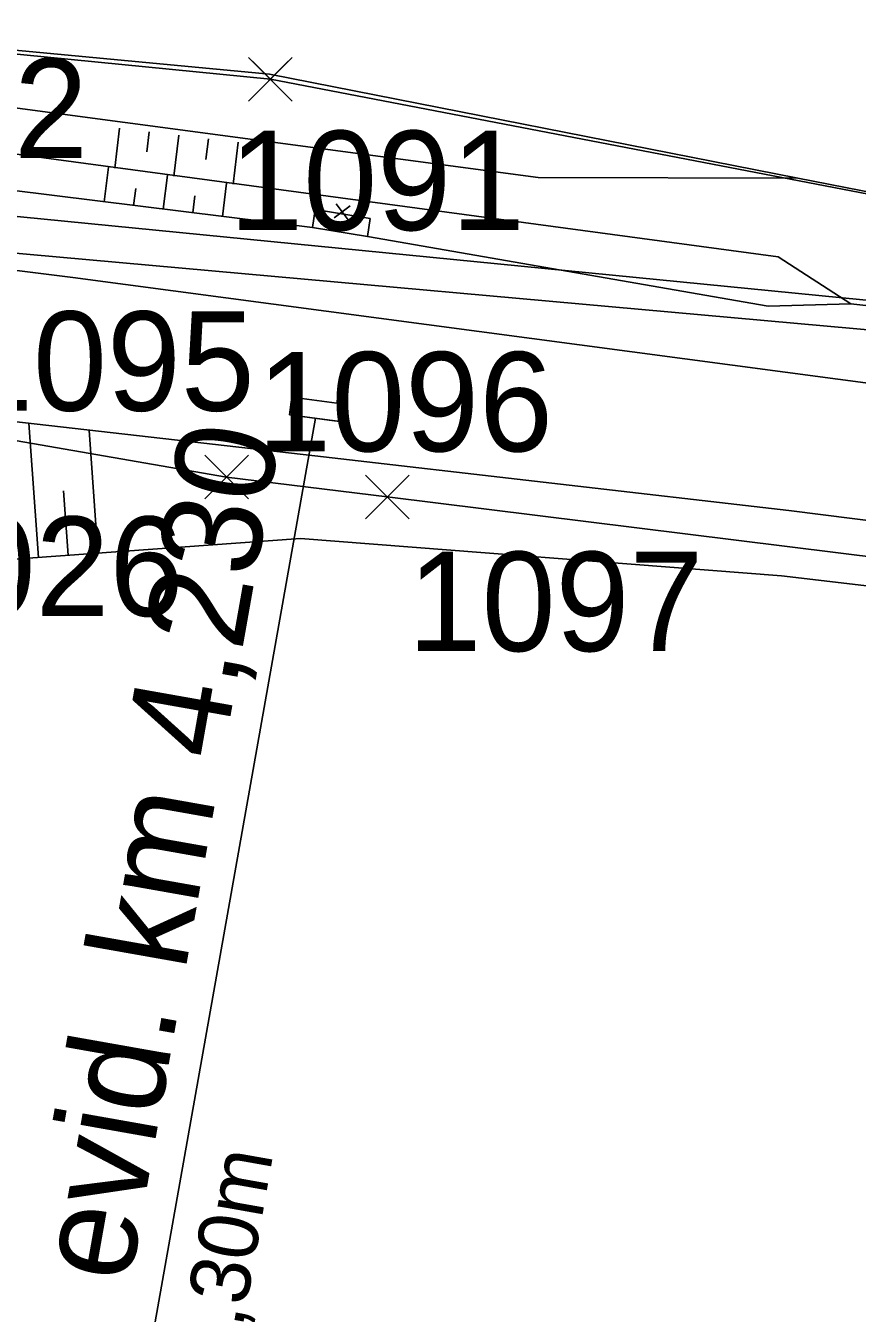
# Model space of a CAD drawing. Extents: x -738085 to -734426, y -1122197 to -1119748.
# Drawn here: x -737329.62 to -737308.71, y -1121446.65 to -1121414.26 of the extents above; entities that cross this region are included whole.
import ezdxf

# ---------------------------------------------------------------- set-up
doc = ezdxf.new("R2010")
doc.units = 0
for name, color, linetype in [('SŽDC', 7, 'Continuous'), ('Vrstva 1', 7, 'Continuous'), ('Vrstva 17', 7, 'Continuous'), ('Vrstva 19', 7, 'Continuous'), ('Vrstva 48', 7, 'Continuous'), ('Vrstva 49', 7, 'Continuous'), ('Vrstva 60', 7, 'Continuous'), ('Vrstva 63', 7, 'Continuous')]:
    doc.layers.add(name, color=color, linetype=linetype)

msp = doc.modelspace()

# ---------------------------------------------------------------- linework, layer by layer
at = {"layer": 'SŽDC'}
for p, q in [((-737336.44, -1121414.32), (-737323.47, -1121415.6)), ((-737323.47, -1121415.6), (-737307.99, -1121418.58)), ((-737296.15, -1121429.13), (-737320.53, -1121426.11))]:
    msp.add_line(p, q, dxfattribs=at)
msp.add_lwpolyline([(-737320.53, -1121426.11), (-737324.57, -1121425.61), (-737331.3, -1121424.45)], dxfattribs=at)
at = {"layer": 'Vrstva 1'}
msp.add_lwpolyline([(-737302.818, -1121423.992), (-737322.068, -1121421.435), (-737328.438, -1121420.593), (-737334.371, -1121419.848), (-737341.175, -1121419.077), (-737346.172, -1121418.626), (-737355.365, -1121418.093), (-737364.193, -1121418.049), (-737371.056, -1121418.37), (-737378.944, -1121419.134), (-737386.424, -1121420.242), (-737394.37, -1121421.821), (-737402.265, -1121423.869), (-737409.266, -1121426.074), (-737416.847, -1121428.911), (-737423.861, -1121431.965), (-737430.654, -1121435.335), (-737438.054, -1121439.528), (-737442.947, -1121442.622), (-737447.091, -1121445.439), (-737453.01, -1121449.85), (-737458.733, -1121454.549), (-737464.941, -1121460.218), (-737469.915, -1121465.238)], dxfattribs=at)
msp.add_lwpolyline([(-737302.818, -1121423.992), (-737322.068, -1121421.435), (-737328.438, -1121420.593), (-737334.371, -1121419.848), (-737341.175, -1121419.077), (-737346.172, -1121418.626), (-737355.365, -1121418.093), (-737364.193, -1121418.049), (-737371.056, -1121418.37), (-737378.944, -1121419.134), (-737386.424, -1121420.242), (-737394.37, -1121421.821), (-737402.265, -1121423.869), (-737409.266, -1121426.074), (-737416.847, -1121428.911), (-737423.861, -1121431.965), (-737430.654, -1121435.335), (-737438.054, -1121439.528), (-737442.947, -1121442.622), (-737447.091, -1121445.439), (-737453.01, -1121449.85), (-737458.733, -1121454.549), (-737464.941, -1121460.218), (-737469.915, -1121465.238)], dxfattribs=at)
at = {"layer": 'Vrstva 17'}
msp.add_lwpolyline([(-737220.546, -1121428.935), (-737265.552, -1121424.89), (-737285.353, -1121422.953), (-737310.199, -1121418.093), (-737323.493, -1121415.476), (-737336.393, -1121414.255)], dxfattribs=at)
at = {"layer": 'Vrstva 19'}
for p, q in [((-737322.341, -1121418.882), (-737322.413, -1121419.333)), ((-737322.341, -1121418.882), (-737322.413, -1121419.333)), ((-737322.341, -1121418.882), (-737320.961, -1121419.103)), ((-737320.961, -1121419.103), (-737321.028, -1121419.555)), ((-737321.028, -1121419.555), (-737320.961, -1121419.103)), ((-737321.028, -1121419.555), (-737322.413, -1121419.333)), ((-737322.987, -1121424.044), (-737322.926, -1121423.597)), ((-737321.59, -1121424.228), (-737321.545, -1121423.785)), ((-737322.338, -1121424.129), (-737328.967, -1121461.535))]:
    msp.add_line(p, q, dxfattribs=at)
for points in [[(-737322.341, -1121418.882), (-737322.341, -1121418.882), (-737320.961, -1121419.103), (-737320.961, -1121419.103)], [(-737322.987, -1121424.044), (-737322.926, -1121423.597), (-737321.545, -1121423.785), (-737321.59, -1121424.228), (-737322.987, -1121424.044)], [(-737322.987, -1121424.044), (-737322.926, -1121423.597), (-737321.545, -1121423.785), (-737321.59, -1121424.228), (-737322.987, -1121424.044)], [(-737322.987, -1121424.044), (-737322.987, -1121424.044), (-737322.668, -1121424.086)], [(-737322.668, -1121424.086), (-737322.668, -1121424.086), (-737321.99, -1121424.175), (-737321.99, -1121424.175)], [(-737321.99, -1121424.175), (-737321.59, -1121424.228), (-737321.59, -1121424.228)]]:
    msp.add_lwpolyline(points, dxfattribs=at)
at = {"layer": 'Vrstva 48'}
for p, q in [((-737327.263, -1121416.832), (-737327.382, -1121417.839)), ((-737326.518, -1121416.92), (-737326.578, -1121417.429)), ((-737325.773, -1121417.008), (-737325.895, -1121418.038)), ((-737325.028, -1121417.096), (-737325.09, -1121417.617)), ((-737324.284, -1121417.184), (-737324.408, -1121418.237)), ((-737327.654, -1121418.683), (-737327.546, -1121417.817)), ((-737326.165, -1121418.868), (-737326.06, -1121418.016)), ((-737324.677, -1121419.052), (-737324.573, -1121418.215)), ((-737326.91, -1121418.775), (-737326.856, -1121418.346)), ((-737325.421, -1121418.96), (-737325.369, -1121418.538)), ((-737329.304, -1121427.631), (-737329.548, -1121424.253)), ((-737327.808, -1121427.524), (-737328.032, -1121424.426)), ((-737328.556, -1121427.577), (-737328.673, -1121425.958))]:
    msp.add_line(p, q, dxfattribs=at)
at = {"layer": 'Vrstva 49'}
for p, q in [((-737310.692, -1121420.073), (-737334.626, -1121416.845)), ((-737321.463, -1121418.783), (-737321.861, -1121419.087)), ((-737321.51, -1121419.134), (-737321.814, -1121418.736)), ((-737308.871, -1121421.248), (-737310.692, -1121420.073)), ((-737285.466, -1121423.951), (-737308.871, -1121421.248))]:
    msp.add_line(p, q, dxfattribs=at)
for points in [[(-737285.353, -1121422.953), (-737310.199, -1121418.093), (-737316.732, -1121418.077), (-737334.06, -1121415.764)], [(-737308.871, -1121421.248), (-737310.948, -1121421.309), (-737321.028, -1121419.555), (-737322.413, -1121419.333), (-737339.798, -1121417.177)], [(-737310.424, -1121426.453), (-737322.355, -1121425.073), (-737338.909, -1121423.185)], [(-737310.424, -1121426.453), (-737286.417, -1121429.492), (-737275.445, -1121430.823), (-737274.622, -1121430.932), (-737264.195, -1121432.22), (-737232.428, -1121436.471), (-737211.461, -1121439.212), (-737210.668, -1121439.317), (-737183.931, -1121442.812), (-737153.07, -1121447.155), (-737152.28, -1121447.279), (-737151.312, -1121447.32), (-737132.329, -1121451.655), (-737115.312, -1121456.236), (-737098.744, -1121461.422), (-737083.523, -1121467.943), (-737082.795, -1121468.275), (-737082.23, -1121468.539), (-737062.886, -1121477.934), (-737046.921, -1121487.27), (-737045.253, -1121485.972)], [(-737310.615, -1121428.097), (-737322.711, -1121427.156), (-737337.814, -1121428.245)], [(-737045.253, -1121485.972), (-737046.649, -1121488.977), (-737063.799, -1121479.293), (-737083.111, -1121469.626), (-737099.88, -1121463.719), (-737115.418, -1121458.068), (-737133.051, -1121454.139), (-737151.026, -1121450.601), (-737184.195, -1121445.275), (-737232.181, -1121438.432), (-737264.79, -1121434.282), (-737286.451, -1121430.891), (-737310.615, -1121428.097)]]:
    msp.add_lwpolyline(points, dxfattribs=at)
at = {"layer": 'Vrstva 60'}
for p, q in [((-737323.02, -1121416.05), (-737324.02, -1121415.05)), ((-737323.92, -1121416.05), (-737322.92, -1121415.05)), ((-737323.02, -1121415.15), (-737324.02, -1121416.15)), ((-737323.92, -1121415.15), (-737322.92, -1121416.15)), ((-737323.47, -1121415.6), (-737323.47, -1121415.6)), ((-737324.12, -1121426.06), (-737325.12, -1121425.06)), ((-737325.02, -1121426.06), (-737324.02, -1121425.06)), ((-737324.12, -1121425.16), (-737325.12, -1121426.16)), ((-737325.02, -1121425.16), (-737324.02, -1121426.16)), ((-737324.57, -1121425.61), (-737324.57, -1121425.61)), ((-737320.08, -1121426.56), (-737321.08, -1121425.56)), ((-737320.08, -1121425.66), (-737321.08, -1121426.66)), ((-737320.98, -1121426.56), (-737319.98, -1121425.56)), ((-737320.98, -1121425.66), (-737319.98, -1121426.66)), ((-737320.53, -1121426.11), (-737320.53, -1121426.11))]:
    msp.add_line(p, q, dxfattribs=at)
at = {"layer": 'Vrstva 63'}
for p in [(-737364.617, -1121415.627), (-737376.128, -1121415.817)]:
    msp.add_line(p, (-737220.606, -1121429.814), dxfattribs=at)

# ---------------------------------------------------------------- texts
at = {"layer": 'Vrstva 19'}
for s, height, p in [('evid. km 4,230', 2.5, (-737327.01, -1121445.94)), ('sv. 0,70m vol.v.0,30m', 1.5, (-737326.802, -1121461.859))]:
    msp.add_text(s, height=height, rotation=79.95, dxfattribs=at).set_placement(p)
at = {"layer": 'Vrstva 60'}
for s, p in [('1092', (-737335.497, -1121417.581)), ('1091', (-737324.502, -1121419.398)), ('1095', (-737331.3, -1121423.942)), ('1096', (-737323.797, -1121424.963)), ('3026', (-737333.096, -1121429.106)), ('1097', (-737320.014, -1121429.99))]:
    msp.add_text(s, height=2.5, dxfattribs=at).set_placement(p)

doc.saveas('drawing.dxf')
